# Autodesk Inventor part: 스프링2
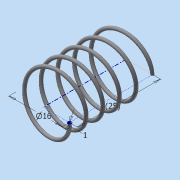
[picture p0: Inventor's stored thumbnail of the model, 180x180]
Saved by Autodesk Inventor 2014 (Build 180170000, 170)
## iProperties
Created: 2015-06
Part Number: 스프링2
Material: 강철, 연강
Document SubType Name: Modeling
Designer: Administrator
Density: 7.86 g/cm^3
Appearance: 강철
Mass: 1.52988 g
Surface Area: 7.87024 cm^2
Volume: 0.194641 cm^3
Author: Administrator
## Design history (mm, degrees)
sketch "스케치1"
  geometry: L1 (0, 0)-(8, 0); L2 (8, 0)-(8, 14.5); L3 (8, 14.5)-(0, 14.5); L4 (0, 14.5)-(0, 0); C1 r 0.5 at (8, 0)
  constraints: 8 end point, 2 parallel, 1 centre point, 1 coincident, 1 horizontal, 1 perpendicular
  dimensions: "d0" = 1 diameter of C1; "d1" = 16 diameter of L2 L4; "d2" = 14.5 distance of L1.end L2.end (derived)
feature "코일1" sketch "스케치1" pitch "d3" = 10; turns "d5" = 5; dims "d4" = 14.5 (= d2), "d6" = 0, angle "d7" = 90 deg, angle "d8" = 90 deg, "d9" = 0, "d10" = 0
sketch "스케치2"
  geometry: L1 (-8.5, 0)-(-7.5, 0) reference; 1 further point
  constraints: 1 horizontal alignment
extrude "돌출1" cut sketch "스케치2" distance "d11" = 10; taper "d12" = 0 deg
node "작업 평면1"
sketch "스케치3"
  geometry: L1 (-7.5, 0)-(-8.5, 0) reference; 1 further point
  constraints: 1 horizontal alignment
extrude "돌출2" cut sketch "스케치3" distance "d14" = 10; taper "d15" = 0 deg
node "솔리드1"
node "절단 모서리 투영1"
node "절단 모서리 투영2"
other parameters: "d13" = 14.5 (= d2)
